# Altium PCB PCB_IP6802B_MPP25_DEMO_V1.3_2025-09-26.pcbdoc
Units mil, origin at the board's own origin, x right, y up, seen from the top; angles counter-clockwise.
Board outline 3349 x 3349 mil, 2 copper layers (Top Layer, Bottom Layer); 131 components, 91 nets, 373 pads, 326 vias.
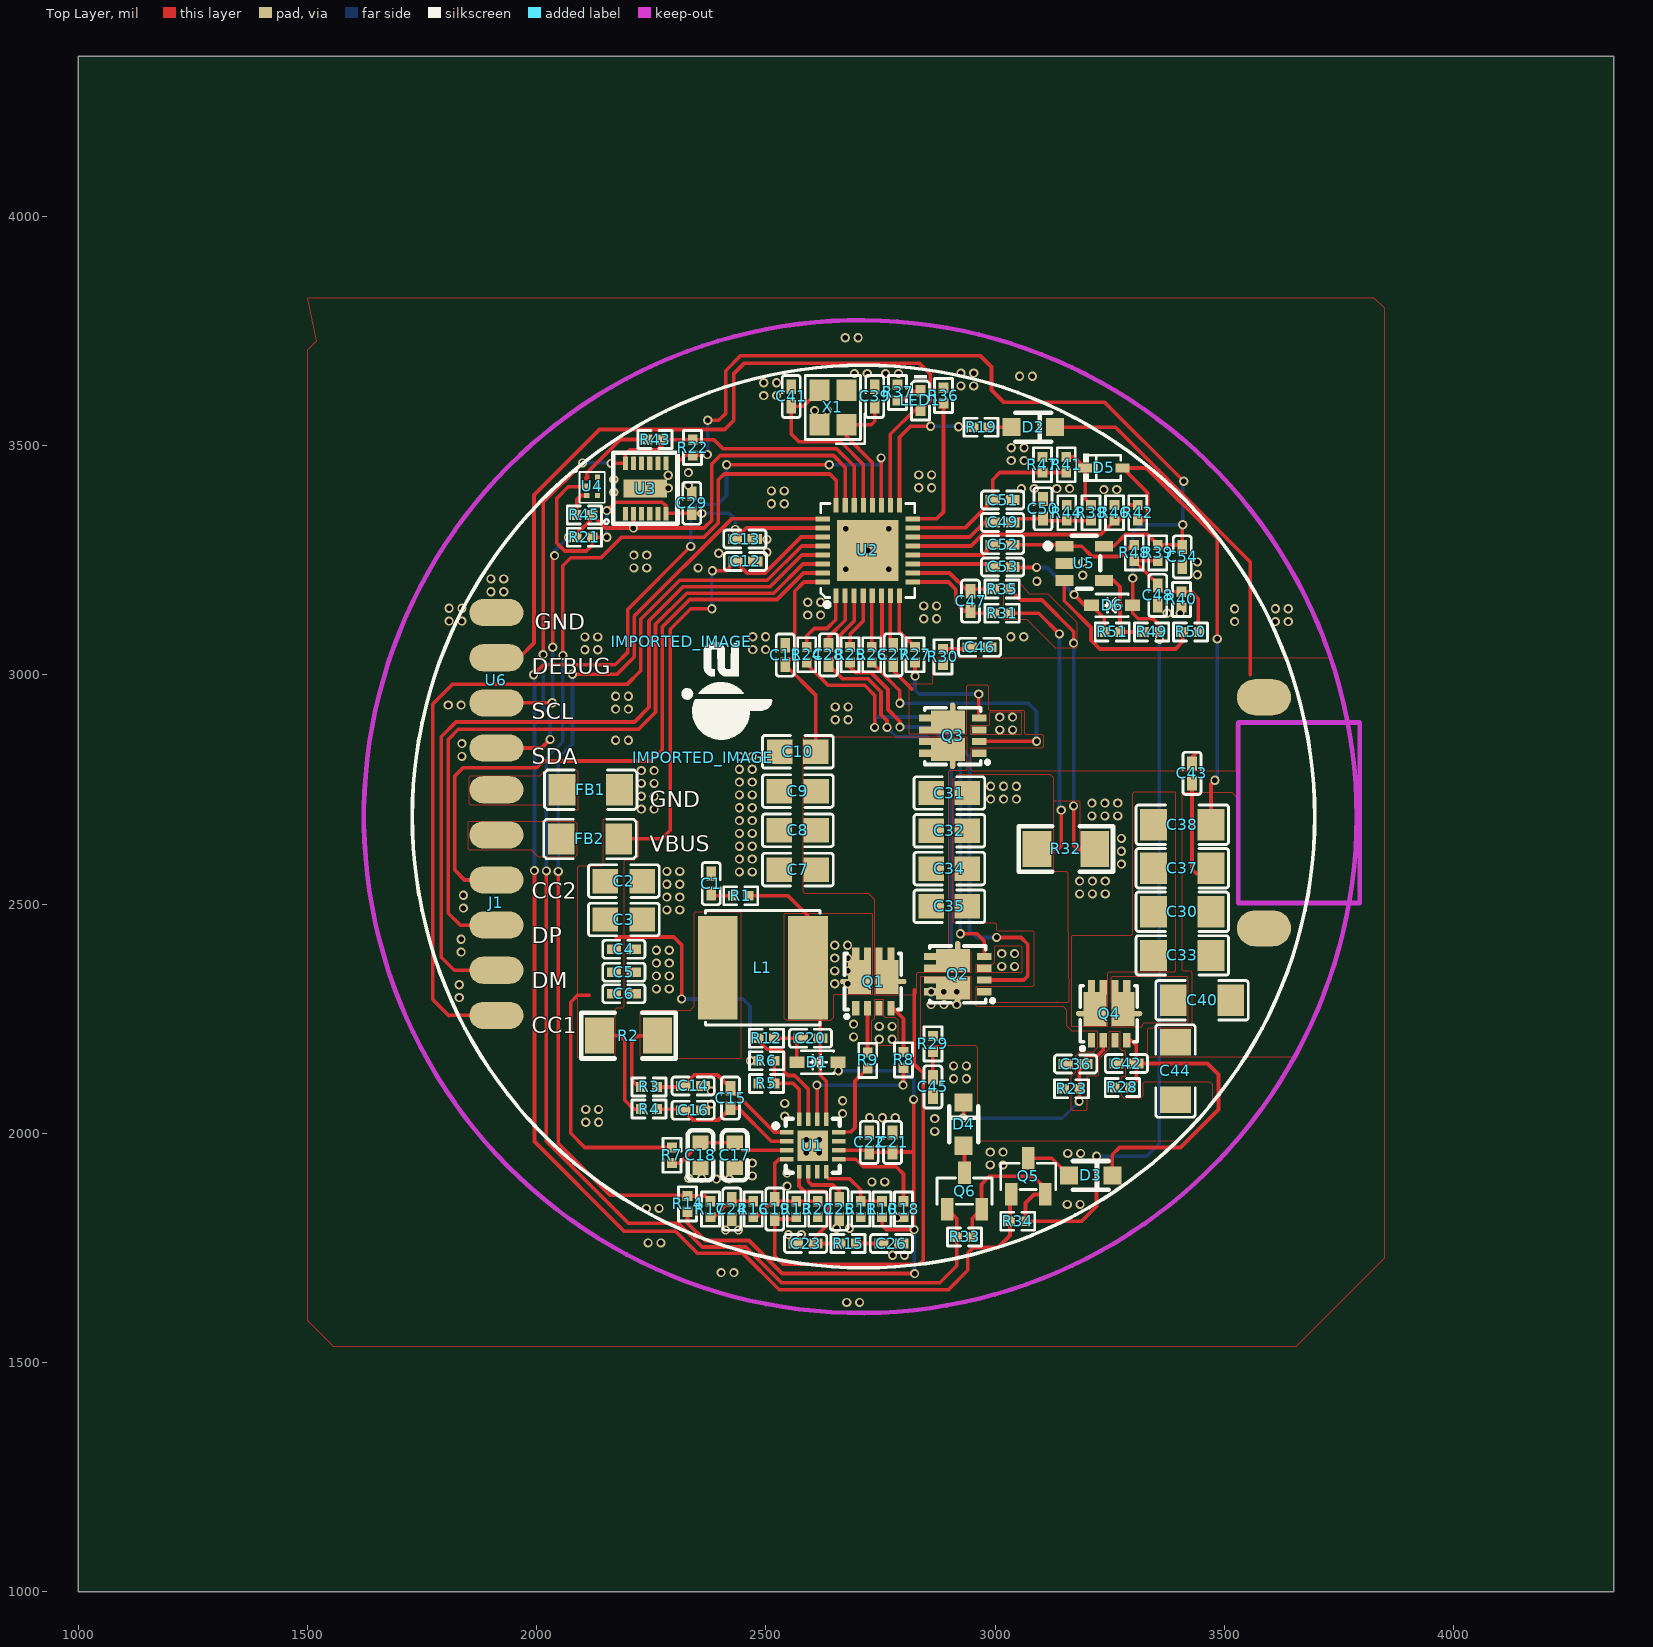
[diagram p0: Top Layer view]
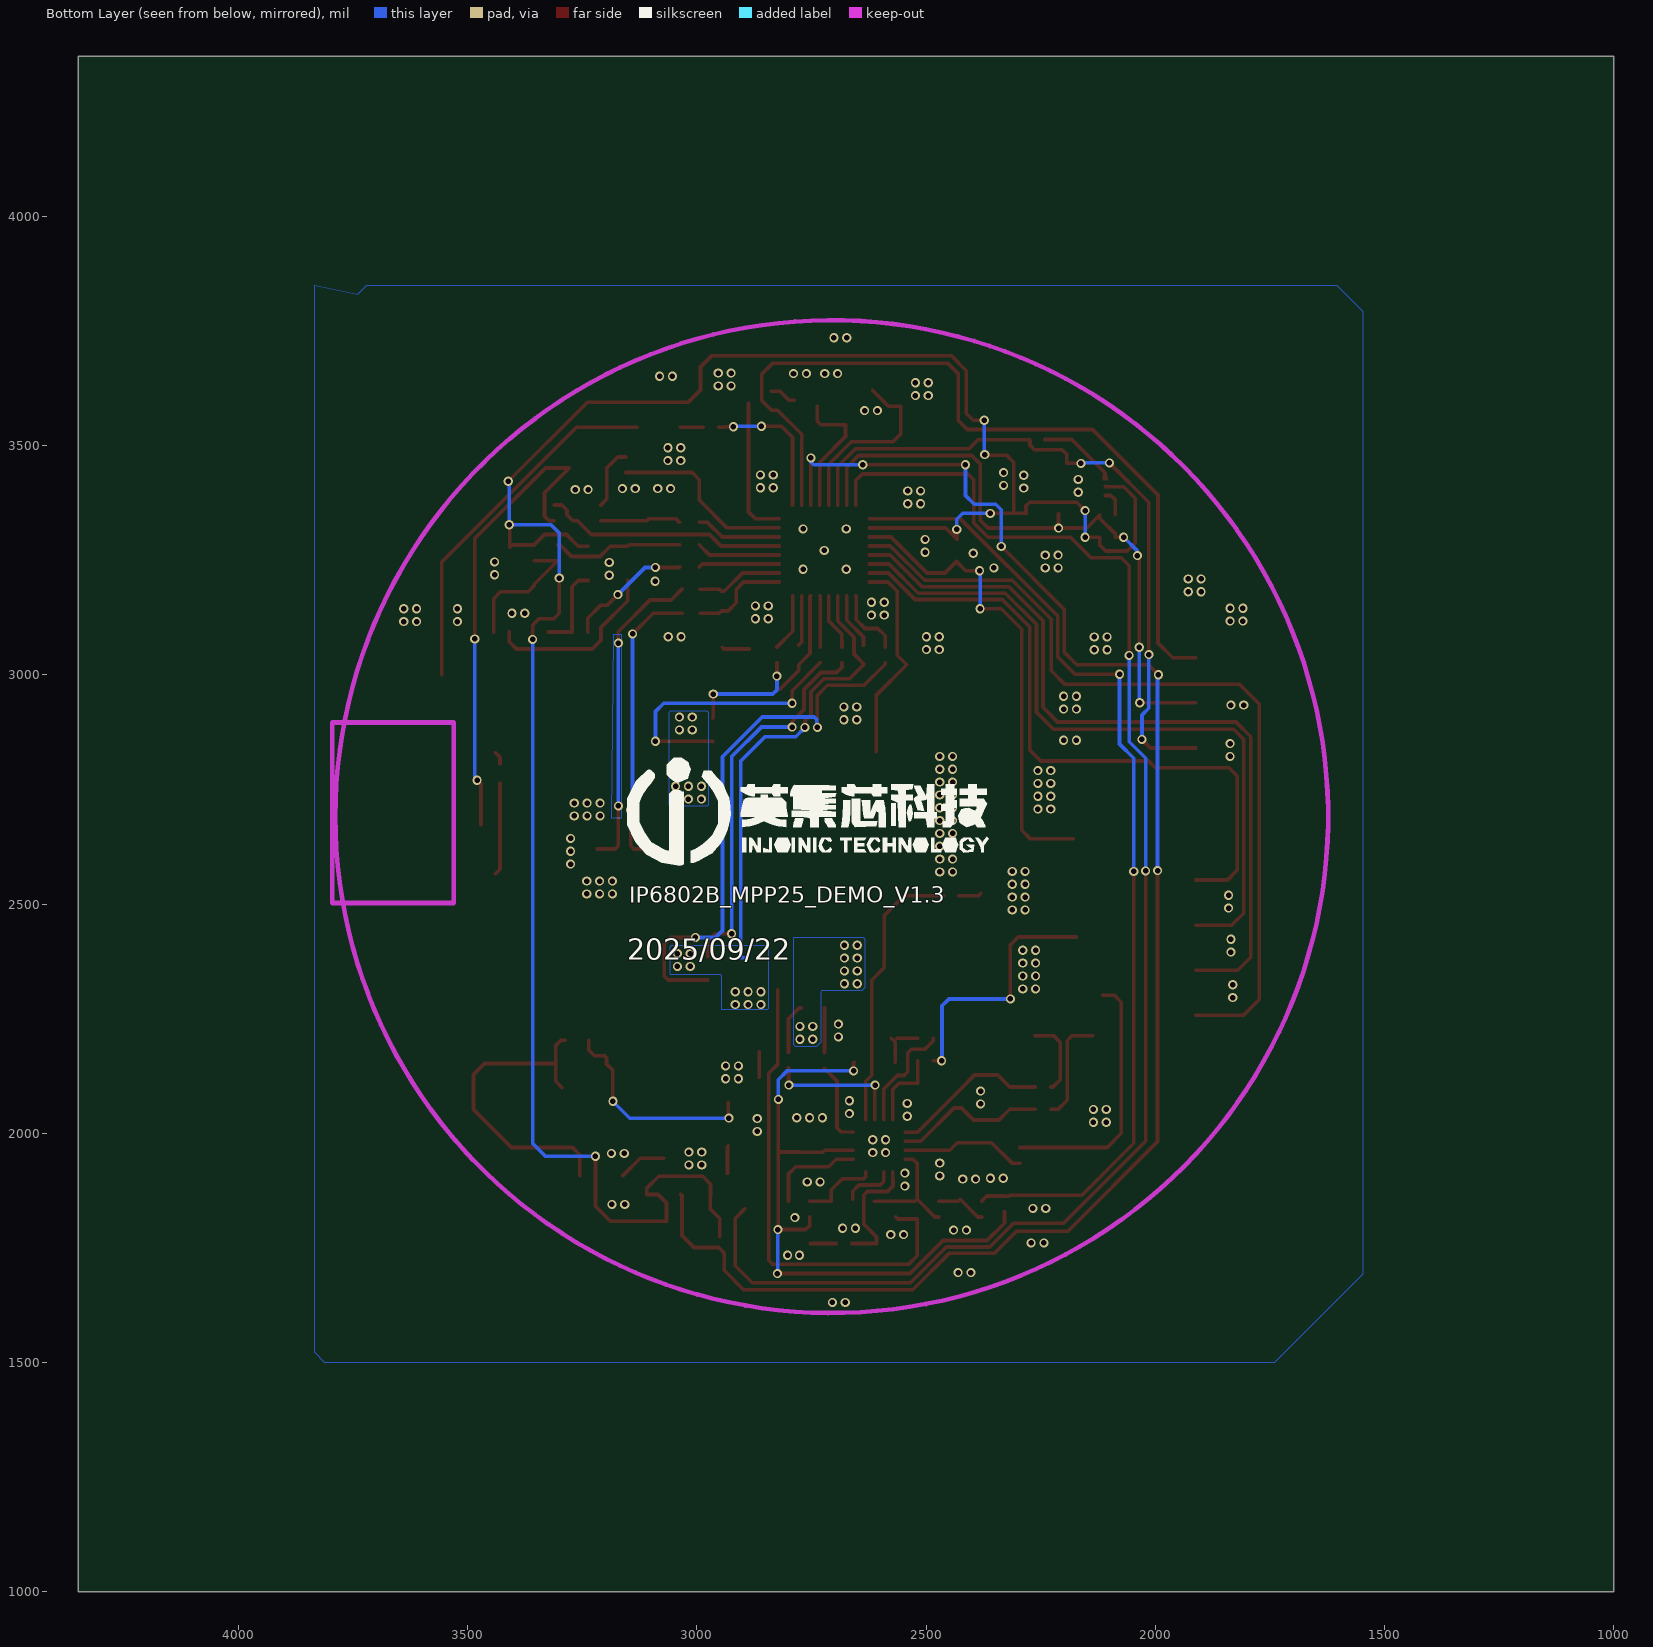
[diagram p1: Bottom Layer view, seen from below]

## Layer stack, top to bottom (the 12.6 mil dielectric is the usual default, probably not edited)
Top Layer: signal copper (thickness not stored)
Dielectric: dielectric 12.6, FR-4, Dk 4.8
Bottom Layer: signal copper (thickness not stored)

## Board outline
4349,1000 1000,1000 1000,4349 4349,4349

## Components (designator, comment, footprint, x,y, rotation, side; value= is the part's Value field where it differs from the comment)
C1 "NC" C0402 2380.5,2544.4 r270 top
C2 "22uF/16V" C0805#1 2190,2550 r0 top
C3 "22uF/16V" C0805#1 2190,2466.2 r0 top
C4 "4.7uF/16V" C0402 2190,2401.2 r0 top
C5 "4.7uF/16V" C0402 2190,2351.2 r0 top
C6 "100nF/16V" C0402 2190,2304.2 r0 top
C7 "22uF/25V" C0805#1 2569.5,2575 r180 top
C8 "22uF/25V" C0805#1 2569.5,2660.7 r180 top
C9 "22uF/25V" C0805#1 2569.5,2746.3 r180 top
C10 "22uF/25V" C0805#2 2569.5,2832 r180 top
C11 "4.7uF/25V" C0402 2542,3043 r270 top
C12 "4.7uF/16V" C0402 2455,3247 r180 top
C13 "4.7uF/6.3V" C0402 2454,3296 r180 top
C14 "15nF/16V" C0402 2341,2103.1 r0 top
C15 "4.7nF/16V" C0402 2422.7,2076.8 r90 top
C16 "15nF/16V" C0402 2341,2050.4 r0 top
C17 "10uF/16V" C0603 2431.7,1952 r270 top
C18 "10uF/16V" C0603 2357,1952 r270 top
C19 "NC" C0402 2519.2,1834.5 r90 top
C20 "100nF/16V" C0402 2597,2207.1 r0 top
C21 "2.2uF/6.3V" C0402 2776,1980 r270 top
C22 "100nF/16V" C0402 2725,1980 r270 top
C23 "10pF/50V" C0402 2586.4,1759.5 r180 top
C24 "100nF/16V" C0402 2425.6,1834.5 r270 top
C25 "100nF/16V" C0402 2659.6,1834.5 r270 top
C26 "3.3nF/50V" C0402 2773.6,1759.5 r0 top
C27 "100nF/16V" C0402 2777.8,3043.5 r90 top
C28 "100nF/16V" C0402 2636.2,3043.5 r90 top
C29 "100nF/16V" C0402 2338,3374 r270 top
C30 "100nF/NPO/100V" C1206 3408,2483 r0 top
C31 "22uF/25V" C0805#2 2900,2742 r0 top
C32 "22uF/25V" C0805#2 2900,2659.7 r0 top
C33 "100nF/NPO/100V" C1206 3408,2388 r0 top
C34 "22uF/25V" C0805#2 2900,2577.3 r0 top
C35 "22uF/25V" C0805#2 2900,2495 r0 top
C36 "100nF/16V" C0402 3175.2,2151 r0 top
C37 "100nF/NPO/100V" C1206 3408,2578 r0 top
C38 "100nF/NPO/100V" C1206 3408,2673 r0 top
C39 "22pF/50V" C0402 2737,3606.9 r90 top
C40 "33nF/NPO/100V" C1206 3450.92,2290 r0 top
C41 "22pF/50V" C0402 2555,3606.9 r270 top
C42 "100nF/16V" C0402 3286,2152 r0 top
C43 "NC" C0402 3429,2785 r90 top
C44 "68nF/NPO/100V" C1206 3393,2136 r90 top
C45 "NC" C0402 2864,2101 r90 top
C46 "NC" C0402 2966,3060 r180 top
C47 "4.7uF/6.3V" C0402 2946.2,3160.4 r270 top
C48 "1uF/6.3V" C0402 3354.5,3173 r270 top
C49 "10nF/50V" C0402 3016,3332.3 r180 top
C50 "10nF/50V" C0402 3104,3362 r270 top
C51 "2.2nF/50V" C0402 3016,3381 r180 top
C52 "10nF/50V" C0402 3016,3283.7 r0 top
C53 "10nF/50V" C0402 3016,3235 r180 top
C54 "1uF/6.3V" C0402 3408,3256.95 r90 top
D1 "1N4148W" SOD-323_L1.7-W1.3-LS2.6-FD-1 2612.18,2155.02 r180 top
D2 "IN5819" SOD-323FH_L2.0-W1.3-LS2.7-RD 3082.96,3540 r180 top
D3 "IN5819" SOD-323FH_L2.0-W1.3-LS2.7-RD 3208,1908 r180 top
D4 "1N4148W" SOD-323FH_L2.0-W1.3-LS2.7-RD 2931,2020 r270 top
D5 "1N4148/100V" SOD-323_L1.7-W1.3-LS2.5-FD 3237,3451 r180 top
D6 "1N4148W" SOD-323_L1.7-W1.3-LS2.6-FD-1 3254.98,3151.22 r180 top
FB1 "0Ω" L1206 2118,2749 r0 top
FB2 "0Ω" L1206 2116,2642 r0 top
IMPORTED_IMAGE "IMPORTED_IMAGE" IMPORTED_IMAGE 2315.84,3071.75 r0 top
IMPORTED_IMAGE "IMPORTED_IMAGE" IMPORTED_IMAGE 2363.7,2819.53 r0 top
J1 "6P焊盘" 6P焊盘 1912,2454 r0 top
L1 "2.2uH" IND-SMD_L6.0-W6.0 2493.01,2361 r0 top
LED1 "LED" LED0402-RD-1-2 2837,3598.16 r270 top
Q1 "AET3125BP" PDFN3333-8_L3.1-W3.1-P0.65-LS3.4-BL-EP 2733.96,2331 r0 top
Q2 "AET3125BP" PDFN3333-8_L3.1-W3.1-P0.65-LS3.4-BL-EP 2918,2347 r90 top
Q3 "AET3125BP" PDFN3333-8_L3.1-W3.1-P0.65-LS3.4-BL-EP 2907,2867 r90 top
Q4 "AER6125AP" PDFN3333-8_L3.1-W3.1-P0.65-LS3.4-BL-EP 3248.2,2261 r0 top
Q5 "BSS84 PD" SOT-23-3_L2.9-W1.3-P0.95-LS2.4-BR-1 3072,1906 r270 top
Q6 "BSS84 PD" SOT-23-3_L2.9-W1.3-P0.95-LS2.4-BR-1 2933,1874.07 r270 top
R1 "NC" R0402 2445,2518 r180 top
R2 "1.5mR/1%" R1206_1 2200,2213 r180 top
R3 "0R/1%" R0402 2245,2101 r0 top
R4 "0R/1%" R0402 2245,2052.7 r0 top
R5 "NC" R0402 2501,2108.8 r0 top
R6 "20K/1%" R0402 2501,2157.9 r0 top
R7 "0R/1%" R0402 2295,1952 r270 top
R8 "0R/1%" R0402 2800,2160 r270 top
R9 "0R/1%" R0402 2722,2159 r90 top
R10 "0R/1%" R0402 2753.2,1834.5 r90 top
R11 "NC" R0402 2706.4,1834.5 r270 top
R12 "0R/1%" R0402 2501,2207 r0 top
R13 "120K/1%" R0402 2566,1834.5 r270 top
R14 "10K/1%" R0402 2329,1846 r90 top
R15 "18K/1%" R0402 2679,1759.5 r0 top
R16 "10K/1%" R0402 2472.4,1834.5 r90 top
R17 "27K/1%" R0402 2378.8,1834.5 r90 top
R18 "200K/1%" R0402 2800,1834.5 r270 top
R19 "100R/5%" R0402 2969,3540 r180 top
R20 "7.5K/1%" R0402 2612.8,1834.5 r270 top
R21 "4.7K/5%" R0402 2104,3300 r180 top
R22 "4.7K/5%" R0402 2340,3495.5 r90 top
R23 "10K/5%" R0402 3166.4,2097 r0 top
R24 "0R/1%" R0402 2589,3043.5 r90 top
R25 "0R/1%" R0402 2683.4,3043.5 r90 top
R26 "0R/1%" R0402 2730.6,3043.5 r90 top
R27 "0R/1%" R0402 2825,3043.5 r90 top
R28 "10K/5%" R0402 3277.2,2100 r0 top
R29 "NC" R0402 2864,2195 r270 top
R30 "NC" R0402 2886,3039 r90 top
R31 "2R/1%" R0402 3015,3134 r0 top
R32 "20mR" R1206_1 3154,2620 r180 top
R33 "100K/5%" R0402 2933,1774 r180 top
R34 "100K/5%" R0402 3049.09,1808 r180 top
R35 "2R/1%" R0402 3015,3186.8 r0 top
R36 "100K" R0402 2887,3609 r270 top
R37 "1K/1%" R0402 2787,3615.7 r270 top
R38 "510R/1%" R0402 3209,3353.2 r270 top
R39 "100K/1%" R0402 3354.5,3265.79 r270 top
R40 "100K/1%" R0402 3406,3164.16 r270 top
R41 "100K/1%" R0402 3155,3458 r90 top
R42 "51K/1%" R0402 3311,3353.2 r270 top
R43 "240R/1%" R0402 2258,3513 r0 top
R44 "NC" R0402 3156,3353.2 r90 top
R45 "240R/1%" R0402 2104,3348.6 r0 top
R46 "51K/1%" R0402 3260,3353.2 r270 top
R47 "6.8K/1%" R0402 3103,3458 r270 top
R48 "200K/1%" R0402 3303,3265.79 r90 top
R49 "4.7K/1%" R0402 3341,3093.4 r0 top
R50 "10K/1%" R0402 3426,3093.4 r180 top
R51 "5.1K/1%" R0402 3255,3093.4 r180 top
U1 "IP6752" TQFN-16_L3.0-W3.0-P0.50-BL-EP1.7 2601.97,1973.03 r270 top
U2 "IP6802" QFN-32_L5.0-W5.0-P0.50-BL-EP3.4 2722,3271 r0 top
U3 "FM1210" FM1230 2312,3329 r90 top
U4 "T91-206" DFN6_I2C 2097.2,3379.2 r0 top
U5 "BL321" SOT-23-5_L2.9-W1.6-P0.95-LS2.8-BR 3194.02,3242.97 r180 top
U6 "4P端口" 4P焊盘 1912,3037 r180 top
X1 "24M" CRYSTAL-SMD_4P-L2.5-W2.0-BL 2646,3582.88 r90 top

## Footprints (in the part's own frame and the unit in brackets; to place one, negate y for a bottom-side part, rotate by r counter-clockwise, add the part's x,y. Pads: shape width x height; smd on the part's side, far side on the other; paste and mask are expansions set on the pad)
4P焊盘 [mm]
  oval 3x1.5 smd paste+0 mask+0.051: 1(0,5) 2(0,2.5) 3(0,0) 4(0,-2.5)
6P焊盘 [mm]
  oval 3x1.5 smd paste+0 mask+0.102: 1(0,-5) 2(0,-2.5) 3(0,0) 4(0,2.5) 5(0,5) 6(0,7.5)
C0402 [mm]
  rect 0.79x0.54 smd paste-100 mask+0.051: 1(-0.545,0) 2(0.545,0)
  silkscreen extent -1.17,-0.5 1.17,0.5
C0603 [mm]
  rect 0.8x0.9 smd paste+0 mask+0.051: 1(-0.7,0) 2(0.7,0)
  silkscreen extent -1.39,-0.71 1.39,0.71
C0805#1 [mm]
  rect 1.41x1.35 smd paste-100 mask+0.051: 1(-1.03,0) 2(1.03,0)
  silkscreen extent -1.96,-0.9 1.96,0.9
C0805#2 [mm]
  rect 1.41x1.35 smd paste-100 mask+0.051: 1(-1,0) 2(1,0)
  silkscreen extent -1.96,-0.9 1.96,0.9
C1206 [mm]
  rect 1.485x1.728 smd paste-100 mask+0.051: 1(-1.593,0) 2(1.593,0)
  silkscreen extent -2.56,-1.09 2.56,1.09
CRYSTAL-SMD_4P-L2.5-W2.0-BL [mm]
  rect 1.2x1.1 smd paste+0 mask+0.051: 1(-0.95,-0.75) 2(0.95,-0.75) 3(0.95,0.75) 4(-0.95,0.75)
  silkscreen extent -2.01,-1.76 1.78,1.53
DFN6_I2C [mm]
  rect 0.3x0.3 smd paste+0 mask+0.051: 2(0.3,0.8) 3(0.3,0.3) 4(0.9,0.3) 5(0.9,0.8) 6(0.9,1.3)
  Top Layer region: 0.3,1.45 0.45,1.45 0.45,1.15 0.15,1.15 0.15,1.3
  silkscreen extent -0.34,-0.1 1.3,1.69
FM1230 [mm]
  rect 0.75x0.29 smd paste+0: 1(0.559,3.014) 2(0.559,2.564) 3(0.559,2.114) 4(0.559,1.664) 5(0.559,1.214) 6(0.559,0.764) 7(3.353,0.764) 8(3.353,1.214) 9(3.353,1.664) 10(3.353,2.114) 11(3.353,2.564) 12(3.353,3.014)
  rect 1x2.4 smd paste+0: 13(1.968,1.905)
  silkscreen extent 0,0.13 3.94,4.19
IMPORTED_IMAGE [mil]
  silkscreen extent 0,-214 198,0
IND-SMD_L6.0-W6.0 [mm]
  rect 2.2x5.72 smd paste+0 mask+0.051: 1(-2.5,0) 2(2.5,0)
  silkscreen extent -3.18,-3.18 3.18,3.18
L1206 [mm]
  rect 1.485x1.728 smd paste-100 mask+0.051: 1(-1.593,0) 2(1.593,0)
  silkscreen extent -2.56,-1.09 2.56,1.09
LED0402-RD-1-2 [mm]
  rect 0.636x0.54 smd paste-100 mask+0.051: 1(0.538,0) 2(-0.538,0)
  silkscreen extent -1.39,-0.54 1.09,0.54
PDFN3333-8_L3.1-W3.1-P0.65-LS3.4-BL-EP [mm]
  rect 0.4x0.8 smd paste-100 mask+0.051: 1(-0.975,-1.47) 2(-0.325,-1.47) 3(0.325,-1.47) 4(0.975,-1.47) 5(0.975,1.47) 6(0.325,1.47) 7(-0.325,1.47) 8(-0.975,1.47)
  rect 1.275x1.88 smd paste-100 mask+0.05: 6(0.765,0.254)
  oval 0.635x0.3 smd paste-100 mask+0.05: 6(1.524,0) 8(-1.524,0)
  rect 1.275x1.88 smd paste-100 mask+0.051: 8(-0.772,0.254)
  silkscreen extent -1.59,-2.03 1.56,1.55
QFN-32_L5.0-W5.0-P0.50-BL-EP3.4 [mm]
  rect 0.28x0.8 smd paste-100 mask+0.05: 1(-1.75,-2.5) 2(-1.251,-2.5) 3(-0.751,-2.5) 4(-0.251,-2.5) 5(0.249,-2.5) 6(0.749,-2.5) 7(1.249,-2.5) 8(1.749,-2.5) 17(1.752,2.5) 18(1.251,2.5) 19(0.752,2.5) 20(0.251,2.5) 21(-0.248,2.5) 22(-0.749,2.5) 23(-1.248,2.5) 24(-1.749,2.5)
  rect 0.8x0.28 smd paste-100 mask+0.05: 9(2.5,-1.748) 10(2.5,-1.248) 11(2.5,-0.748) 12(2.5,-0.248) 13(2.5,0.252) 14(2.5,0.752) 15(2.5,1.252) 16(2.5,1.752) 25(-2.5,1.75) 26(-2.5,1.25) 27(-2.5,0.75) 28(-2.5,0.25) 29(-2.5,-0.25) 30(-2.5,-0.75) 31(-2.5,-1.25) 32(-2.5,-1.75)
  rect 3.4x3.4 smd paste-100 mask+0.05: 33(0,0)
  silkscreen extent -2.6,-3.12 2.6,2.6
R0402 [mm]
  rect 0.566x0.54 smd paste-100 mask+0.051: 1(-0.433,0) 2(0.433,0)
  silkscreen extent -0.94,-0.5 0.94,0.5
R1206_1 [mil]
  rect 63x78.74 smd paste+0 mask+1.97: 1(-62.99,0) 2(62.99,0)
  silkscreen extent -103,-50 103,50
SOD-323_L1.7-W1.3-LS2.5-FD [mm]
  rect 0.78x0.5 smd paste+0 mask+0.051: 1(-1.04,0) 2(1.04,0)
  silkscreen extent -0.93,-0.78 1.15,0.78
SOD-323_L1.7-W1.3-LS2.6-FD-1 [mm]
  rect 0.83x0.63 smd paste+0 mask+0.05: 1(-1.14,0) 2(1.14,0)
  silkscreen extent -0.89,-0.63 0.89,0.64
SOD-323FH_L2.0-W1.3-LS2.7-RD [mm]
  rect 1x1 smd paste+0 mask+0.051: 1(-1.2,0) 2(1.2,0)
  silkscreen extent -1,-0.8 1,0.8
SOT-23-3_L2.9-W1.3-P0.95-LS2.4-BR-1 [mm]
  rect 1.25x0.7 smd paste+0 mask+0.051: 1(1,-0.95) 2(1,0.95) 3(-1,0)
  silkscreen extent -0.73,-1.53 0.73,1.53
SOT-23-5_L2.9-W1.6-P0.95-LS2.8-BR [mm]
  rect 1x0.6 smd paste+0 mask+0.05: 1(1.1,-0.95) 2(1.1,0) 3(1.1,0.95) 4(-1.1,0.95) 5(-1.1,-0.95)
  silkscreen extent -0.89,-1.52 2.16,1.4
TQFN-16_L3.0-W3.0-P0.50-BL-EP1.7 [mm]
  rect 0.25x0.75 smd paste-100 mask+0.051: 1(-0.748,-1.45) 2(-0.249,-1.45) 3(0.252,-1.45) 4(0.751,-1.45) 9(0.75,1.45) 10(0.25,1.45) 11(-0.25,1.45) 12(-0.749,1.45)
  rect 0.75x0.25 smd paste-100 mask+0.051: 5(1.45,-0.75) 6(1.45,-0.25) 7(1.45,0.25) 8(1.45,0.75) 13(-1.45,0.75) 14(-1.45,0.25) 15(-1.45,-0.25) 16(-1.45,-0.75)
  rect 1.7x1.7 smd paste-100 mask+0.051: 17(0,0)
  silkscreen extent -1.5,-2.17 1.5,1.5

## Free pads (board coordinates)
  oval 118.11x78.74 smd paste+0 mask+2: 2(3586,2447) 2(3586,2951.01)

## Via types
v1: diameter 20, hole 12, Top Layer to Bottom Layer, tented both sides, 326 vias

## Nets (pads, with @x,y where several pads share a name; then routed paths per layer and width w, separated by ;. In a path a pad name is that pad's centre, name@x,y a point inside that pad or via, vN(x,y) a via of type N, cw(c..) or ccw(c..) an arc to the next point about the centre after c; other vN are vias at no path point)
BIAS: C21.2 C22.2 D1.1 R10.1 R14.1 U1.10 | length 1437.5
  Top Layer w8: R14.1 2329,1804 2367,1766 2463,1766 2534.99,1694 v1(2824,1694) ; D1.1 2658,2154.09 v1(2658,2136) ; U1.10 2720.39,1963.15 C22.2 ; C22.2 C21.2 ; R10.1 2753.2,1798.8 2762,1790 v1(2823,1790) 2822,1791 2822,1959 ; C21.2@2776,1959 2822,1959 ; v1(2822,2074) 2822,1959
  Bottom Layer w8: v1(2658,2136) 2803,2136 2822,2117 v1(2822,2074) ; v1(2823,1790) 2823,1695 v1(2824,1694)
BST: R12.1 U1.15 | length 248.1
  Top Layer w8: R12.1 2484,2201 2502,2183 2532,2183 2540,2175 2540,2134 2548,2126 2563,2126 2592.2,2096.8 U1.15@2592.2,2030.1
BST1: C28.2 U2.2 | length 122.7
  Top Layer w8: C28.2 2636.2,3082.2 2672.7,3118.7 U2.2
BST2: C27.2 U2.7 | length 110.4
  Top Layer w8: U2.7 2771.16,3071.6 C27.2
C1_2: C1.2 R1.2 | length 49.5
  Top Layer w8: C1.2 2385.43,2517.99 R1.2
C26_1: C26.1 R15.2 | length 56.1
  Top Layer w8: R15.2 C26.1@2752.16,1759.5
C45_2: C45.2 R29.2 | length 55.5
  Top Layer w8: C45.2 R29.2
C46_2: C46.2 R30.2 | length 60.2
  Top Layer w8: R30.2 2940.58,3056.04 C46.2
CC1: J1.1 U2.28 | length 1856.5
  Top Layer w8: J1.1 1808,2257 1773,2292 1773,2936 1816,2979 2197,2979 2227,3009 2227,3121 2312,3206 2503,3206 2577.8,3280.8 U2.28
CC2: J1.4 U2.31 | length 1448
  Top Layer w8: J1.4 1842.6,2552.4 1821,2574 1821,2779 1839,2797 2000,2797 2015,2812 2250,2812 2274,2836 2274,3104 2334,3164 2524,3164 2581.8,3221.8 U2.31
COMP: C23.1 R15.1 U1.5 | length 274.4
  Top Layer w8: U1.5@2572.5,1915.9 2572,1885 2584,1873 2628,1873 2636,1865 2636,1802 2607.9,1773.9 C23.1 ; C23.1 R15.1
D1_2: C20.1 D1.2 R12.2 | length 101
  Top Layer w8: R12.2 2563.3,2207 C20.1@2563.5,2207.2 ; D1.2 2567.33,2198.89 C20.1
D3_2: D3.2 Q5.3 | length 104.2
  Top Layer w8: Q5.3 3123.39,1945.37 D3.2
D4_2: D4.2 Q6.3 | length 60.2
  Top Layer w8: D4.2 2933,1970.76 Q6.3
D5_2: D5.2 R38.1 R41.2 | length 137.2
  Top Layer w8: R41.2 3172.02,3475.04 D5.2 3196.06,3383.14 R38.1
D6_2: C53.1 D6.2 R51.2 | length 276.7
  Top Layer w8: C53.1 3038.46,3234 v1(3090,3234) ; v1(3172,3175) 3195.78,3151.22 D6.2 3238,3123.3 R51.2
  Bottom Layer w8: v1(3090,3234) 3113,3234 v1(3172,3175)
DM: J1.2 U2.29 | length 1719.2
  Top Layer w8: J1.2 1820.4,2355.6 1792,2384 1792,2865 1824,2897 2213,2897 2245,2929 2245,3118 2319,3192 2509,3192 2578.2,3261.2 U2.29
DP: J1.3 U2.30 | length 1582.3
  Top Layer w8: J1.3 1833,2454 1807,2480 1807,2859 1829,2881 2222,2881 2259,2918 2259,3110 2327,3178 2517,3178 2580.5,3241.5 U2.30
DRV1H: R25.2 U2.4 | length 123.7
  Top Layer w8: R25.2 2684,3089.1 2712.1,3117.2 U2.4
DRV1L: R24.2 U2.1 | length 155
  Top Layer w8: R24.2 2589,3085 2605,3101 2633,3101 2652,3120 2652,3171.48 U2.1
DRV2H: R26.2 U2.5 | length 112.5
  Top Layer w8: R26.2 2730.6,3171.39 U2.5
DRV2L: R27.2 U2.8 | length 126.3
  Top Layer w8: U2.8 2790.8,3094.7 R27.2
FB: C19.2 R13.1 R16.1 R20.1 U1.4 | length 265.9
  Top Layer w8: R16.1 2480.7,1817.46 C19.2 2523.62,1851.54 R13.1 R20.1 ; C19.2 2519.2,1934.2 2528.4,1943.4 U1.4
FB1_1: FB1.1 J1.6
FB2_1: FB2.1 J1.5
FOSC: R18.1 U1.9 | length 213.9
  Top Layer w8: U1.9 2695.5,1943.5 2712,1927 2784,1927 2800,1911 R18.1
GND: C1.1 C2.2 C3.2 C4.2 C5.2 C6.2 C7.2 C8.2 C9.2 C10.2 C11.1 C12.1 C13.1 C14.2 C16.2 C17.2 C18.2 C21.1 C22.1 C23.2 C24.2 C25.2 C26.2 C29.1 C39.2 C41.1 C45.1 C46.1 C48.2 C50.1 C51.1 C54.1 FB1.2 Q1.1 R5.1 R11.2 R18.2 R20.2 R32.1 R35.2 R36.1 R37.1 R40.2 R44.2 R46.1 R47.1 U1.11 U1.17 U2.33 U3.7 U3.13 U4.4 U4.5 U4.6 U5.2 U6.4 X1.2 X1.4 | length 693.3
  Top Layer w8: R35.2 3055.84,3163 3102,3163 3171,3094 v1(3171,3069) ; v1(3171,2714) 3171,2627 3178,2620 R32.1
  Bottom Layer w8: v1(3171,2714) v1(3171,3069)
  other v1: 2676,1631 2704,1631 2402,1696 2430,1696 2776,1734 2802,1734 2243,1761 2271,1761 2549,1779 2577,1779 2412,1789 2440,1789 2654,1793 2682,1793 2786,1816 2239,1836 2267,1836 3157,1845 3185,1845 2546,1885 2731,1894 2759,1894 2391.95,1899.99 2419.95,1899.99 2331.61,1901.99 2359.61,1901.99 2470,1907 2546,1913 2989,1931 3017,1931 2470,1935 3158,1956 3186,1956 2588.04,1957.97 2616.04,1957.97 2989,1959 3017,1959 2588.04,1985.97 2616.04,1985.97 2868,2004 2107,2024 2135,2024 2868,2032 2726,2034 2754,2034 2782,2034 2541,2037 2667,2043 2107,2052 2135,2052 2381,2064 2541,2065 2667,2071 2381,2092 2909,2119 2937,2119 2909,2147 2937,2147 2691,2210 2691,2238 1831,2296 2261,2315 2289,2315 1831,2324 2261,2343 2289,2343 2261,2371 2289,2371 1835,2395 2261,2399 2289,2399 1835,2423 2284,2487 2312,2487 1840,2491 2284,2515 2312,2515 1840,2519 3184,2522 3212,2522 3240,2522 2284,2543 2312,2543 3184,2550 3212,2550 3240,2550 2442,2570 2470,2570 2284,2571 2312,2571 3275,2587 2442,2598 2470,2598 3275,2615 2442,2626 2470,2626 3275,2643 2442,2654 2470,2654 2442,2682 2470,2682 3211,2692 3239,2692 3267,2692 2228,2707 2256,2707 2442,2710 2470,2710 3211,2720 3239,2720 3267,2720 2228,2735 2256,2735 2442,2738 2470,2738 2228,2763 2256,2763 2442,2766 2470,2766 2228,2791 2256,2791 2442,2794 2470,2794 1837,2822 2442,2822 2470,2822 1837,2850 2172,2857 2200,2857 2651,2902 2679,2902 2172,2925 2200,2925 2651,2930 2679,2930 1807,2934 1835,2934 2172,2953 2200,2953 2105,3054.5 2133,3054.5 2471,3055 2499,3055 2105,3082.5 2133,3082.5 2471,3083 2499,3083 3034,3083 3062,3083 3522,3116 3611,3116 3639,3116 1809,3117 1837,3117 2844,3122 2872,3122 2591,3130 2619,3130 3375,3134 3403,3134 3522,3144 3611,3144 3639,3144 1809,3145 1837,3145 2844,3150 2872,3150 2591,3158 2619,3158 1900,3181 1928,3181 3091,3204 1900,3209 1928,3209 3191,3217 3441,3218 2674,3230.11 2768,3230.11 2212,3233 2240,3233 2352,3233 3191,3245 3441,3246 2212,3261 2240,3261 2397,3265 2502,3267 2722,3271 2502,3295 2674,3318.11 2768,3318.11 2512,3373 2540,3373 2168,3398 2512,3401 2540,3401 3237,3404 3265,3404 3057,3406 3085,3406 3134,3406 3162,3406 2287,3407 2833,3408 2861,3408 2331,3413 2168,3426 2287,3435 2833,3436 2861,3436 2331,3441 3035,3467 3063,3467 3035,3495 3063,3495 2606,3576 2634,3576 2495,3609 2523,3609 2925,3630 2953,3630 2495,3637 2523,3637 3053,3651 3081,3651 2693,3657 2721,3657 2761,3657 2789,3657 2925,3658 2953,3658 2673,3735 2701,3735
GPIO1: R19.2 U2.17 | length 320.4
  Top Layer w8: U2.17 2791,3518 2815,3542 v1(2859,3542) ; v1(2920,3541) 2937,3541 2938,3540 R19.2
  Bottom Layer w8: v1(2859,3542) 2919,3542 v1(2920,3541)
IDEM1: C53.2 U2.11 | length 176.8
  Top Layer w8: U2.11 2987.99,3241.55 C53.2
ISNS1N: C47.1 R35.1 U2.10 | length 191.4
  Top Layer w8: U2.10 2900.13,3221.87 2940.14,3181.86 C47.1 2951.13,3186.78 R35.1@2993.16,3186.78
ISNS1O: C52.1 U2.12 | length 183.4
  Top Layer w8: U2.12 2972.1,3261.2 C52.1
ISNS1P: C47.2 R31.1 U2.9 | length 217
  Top Layer w8: U2.9 2897.8,3202.2 2914,3186 2914,3157 2932.1,3138.9 C47.2 ; C47.2 2951.13,3134.01 R31.1@2992.16,3134.01
LED1/DEBUG: LED1.1 U2.18 U6.3 | length 1800.5
  Top Layer w8: U6.3 1962,3037 1994,3069 1994,3392 2137,3535 2410,3535 2430,3555 2430,3657 2452,3679 2835,3679 2858,3656 2858,3598 LED1.1 ; U2.18 2771.27,3524.27 2823.97,3576.97 LED1.1
LX: C20.2 L1.2 Q1.3 Q1.7 Q1.8 R1.1 U1.13 | length 608.4
  Top Layer w8: R1.1 2548.01,2517.99 2591.42,2474.58 L1.2 2618.46,2333.96 C20.2 2618.46,2126.54 2631.5,2113.5 U1.13
  other v1: 2747,2205 2775,2205 2747,2233 2775,2233 2650,2326 2678,2326 2650,2354 2678,2354 2650,2382 2678,2382 2650,2410 2678,2410
NONET: 
NTC: R36.2 U2.16 | length 309.8
  Top Layer w8: U2.16 2872,3340 2887,3355 R36.2
OSC_IN: C39.1 U2.20 X1.1 | length 296.5
  Top Layer w8: U2.20 2731.9,3463.1 2675.5,3519.5 X1.1 2729.5,3545.5 2737,3553 C39.1
OSC_OUT: C41.2 U2.21 X1.3 | length 410.3
  Top Layer w8: C41.2 2555,3525 2572,3508 2663,3508 2712.2,3458.8 U2.21 ; C41.2 2581.62,3585.43 X1.3
PWM: R14.2 R17.2 U2.25 | length 2158.1
  Top Layer w8: v1(2047,2571) 2047,1978 2160,1865 2317,1865 2319,1863 R14.2 ; v1(2078,3001) 2175,3001 2212.9,3038.9 2212.9,3127.9 2424.9,3339.9 U2.25 ; R14.2 2367.3,1863.04 R17.2
  Bottom Layer w8: v1(2047,2571) 2047,2818 2078,2849 v1(2078,3001)
Q1_2: Q1.2 R9.2 | length 97.4
  Top Layer w8: Q1.2 2721.21,2176.83 R9.2
Q1_4: Q1.4 R8.1 | length 110.2
  Top Layer w8: Q1.4@2772.39,2273.13 2776.87,2273.13 2800,2250 R8.1
Q4_6: C40.1 Q4.5 Q4.6
Q4_8: C30.1 C33.1 C37.1 C38.1 Q4.7 Q4.8
QDET1: R42.1 R46.2 U2.13 | length 533.4
  Top Layer w8: U2.13 2946.92,3280.92 2972,3306 3229.88,3306 3260,3336.12 3270.1,3336.1 3283,3349 3283,3359 3294.2,3370.2 R42.1
R2_1: L1.1 R2.1 R3.1 | length 170.8
  Top Layer w8: R3.1 2223,2101 2207,2117 2207,2198 2222,2213 R2.1
R5_2: R5.2 R6.2 U1.16 | length 174.5
  Top Layer w8: R5.2 2559.2,2108.8 2572.5,2095.5 U1.16@2572.5,2030.1 ; R5.2 R6.2
R7_2: C17.1 C18.1 R7.2 U1.3 | length 275.2
  Top Layer w8: R7.2 2312.4,1934.96 C18.1 C17.1 2448.14,1963.09 U1.3
R10_2: R10.2 R11.1 U1.8 | length 169.1
  Top Layer w8: U1.8 2631.53,1905.47 2635.83,1901.17 2681.83,1901.17 2706.4,1876.6 R11.1 R10.2
R17_1: C24.1 R16.2 R17.1 | length 111.4
  Top Layer w8: R17.1 2387.1,1817.46 C24.1 2430.02,1851.54 R16.2
R19_1: D2.2 R19.1 | length 49.7
  Top Layer w8: R19.1 D2.2@3035.76,3540
R24_1: Q2.2 R24.1 | length 1197.4
  Top Layer w8: R24.1 2589,3022.9 2635.07,2976.83 2715.17,2976.83 2737,2955 v1(2737,2885) ; Q2.2 3062.2,2334.2 3071,2343 3071,2412 3056,2427 v1(3003,2427)
  Bottom Layer w8: v1@2738,2885 2738,2902 2744,2908 2857,2908 2944,2821 2944,2442 2959,2427 v1(3003,2427)
R25_1: Q2.4 R25.1 | length 842.5
  Top Layer w8: R25.1 2683.4,3016.6 2695,3005 2729,3005 2766,2968 2766,2924 2792,2898 v1(2792,2886) ; v1(2924,2435) 2960,2435 2975.87,2419.13 Q2.4
  Bottom Layer w8: v1(2792,2886) 2859,2886 2924,2821 v1(2924,2435)
R26_1: Q3.2 R26.1 | length 609.9
  Top Layer w8: R26.1 2792,2965.1 v1(2792,2938) ; Q3.2 2965.67,2855 v1(3090,2855)
  Bottom Layer w8: v1(2792,2938) 3072,2938 3090,2920 v1(3090,2855)
R27_1: Q3.4 R27.1 | length 255.2
  Top Layer w8: v1(2825,2997) R27.1 ; v1(2964,2958) 2964,2906.26 Q3.4
  Bottom Layer w8: v1(2825,2997) 2825,2967 2834,2958 v1(2964,2958)
R32_2: C31.2 C32.2 C34.2 C35.2 Q2.1 Q3.3 R31.2 R32.2 | length 646.2
  Top Layer w8: R31.2 3095,3134 v1(3140,3089) ; R32.2 3137,2620 3144,2627 v1(3144,2705)
  Bottom Layer w8: v1(3140,3089) 3140,2709 v1(3144,2705)
  other v1: 2990,2729 3018,2729 3046,2729 2990,2757 3018,2757 3046,2757 3009.74,2879.8 3037.74,2879.8 3009.74,2907.8 3037.74,2907.8
R37_2: LED1.2 R37.2 | length 58.1
  Top Layer w8: R37.2 2798.66,3598.66 2818.19,3618.19 LED1.2@2837,3618.19
R44_1: C49.1 C50.2 R38.2 R44.1 | length 176.8
  Top Layer w8: C49.1@3037.42,3332.3 3045.66,3340.54 C50.2 3108.42,3336.12 3156,3336.12 R38.2@3209,3336.12
R50_2: R50.2 U5.3 | length 390.6
  Top Layer w8: U5.3 3150.7,3161.3 3209,3103 3209,3075 3228,3056 3393,3056 3409,3072 R50.2
R51_1: R49.1 R51.1 U5.4 | length 190.9
  Top Layer w8: U5.4 3258.4,3205.6 3272,3192 R51.1 ; R51.1 R49.1
S1: Q6.1 R33.2 U2.24 | length 3234.8
  Top Layer w8: v1(2021,2572) 2021,1983 2200,1804 2309,1804 2361,1752 2456,1752 2534,1674 2879,1674 2916,1711 R33.2 ; v1(2057,3042) 2057,3238 2074,3255 2140,3255 2185,3300 2365,3300 2396,3331 2396,3425 2409,3438 2639,3438 2653.2,3423.8 U2.24 ; Q6.1 2915.96,1814.34 R33.2
  Bottom Layer w8: v1(2021,2572) 2020.99,2817.99 2057,2854 v1(2057,3042)
S1_CTL: C36.2 D4.1 Q4.2 R23.2 | length 470.7
  Top Layer w8: v1(2930,2033) 2931,2034 D4.1 ; v1(3183,2070) 3183,2096.56 R23.2 3183.44,2137.78 C36.2 3196.66,2164.66 3201,2169 3223,2169 3235.41,2181.41 Q4.2
  Bottom Layer w8: v1(2930,2033) 3146,2033 v1(3183,2070)
S2: Q5.1 R34.2 U2.19 | length 3556.2
  Top Layer w8: v1(1993,3000) 2015,3022 2171,3022 2198.8,3049.8 2198.8,3142.8 v1(2336,3280) ; v1(1995,2573) 1995,1982 2191,1786 2303,1786 2351,1738 2450.1,1738 2529.1,1659 2898,1659 2940,1701 2940,1739 2952,1751 3006,1751 3032,1777 R34.2 ; v1(2414,3458) v1(2638,3458) ; v1(2751,3473) 2751.59,3472.41 U2.19 ; R34.2 3032.05,1864.08 Q5.1
  Bottom Layer w8: v1(1993,3000) 1995,3000 v1(1995,2573) ; v1(2336,3280) 2336,3360 2348,3372 2395,3372 2414,3391 v1(2414,3458) ; v1(2638,3458) 2745,3458 2751,3464 v1(2751,3473)
S2_CTL: C42.2 D3.1 Q4.4 R28.2 | length 706.1
  Top Layer w8: D3.1 3255.2,1953.2 3271,1969 3404,1969 3487,2052 3487,2128 3463,2152 C42.2 ; Q4.4 3295.9,2203.1 3307.5,2191.5 C42.2 ; R28.2 3307.5,2113.2 C42.2
SCL: R21.2 R45.2 U2.23 U3.2 U6.2 | length 1404
  Top Layer w8: U6.2 2033.58,2938.58 v1(2034,2939) ; v1(2035,3060) 2035,3256 v1(2039,3260) ; v1(2069,3300) R21.2 ; R21.2 2087,3307 2121,3341 R45.2 2149.7,3320 v1(2211,3320) ; U3.2@2211,3351 v1(2211,3320) ; U2.23@2672.9,3369.4 2672.9,3452.2 2647,3478 2400,3478 2382,3460 2382,3337 2365,3320 v1(2211,3320)
  Bottom Layer w8: v1(2034,2939) 2035,2940 v1(2035,3060) ; v1(2039,3260) 2039,3270 v1(2069,3300)
SDA: R22.2 R43.2 U2.22 U3.12 U6.1 | length 1511
  Top Layer w8: U6.1 2010.15,2840.15 v1(2029,2859) ; v1(2014,3044) 2014,3376 v1(2100,3462) ; v1(2162,3461) U3.12 2193.34,3480.99 2203.34,3490.99 2263.34,3490.99 2273.34,3500.99 2273.34,3511.3 R43.2 ; R43.2 R22.2 2386.5,3512.5 2406,3493 2654,3493 2692.5,3454.5 U2.22
  Bottom Layer w8: v1(2014,3044) 2014,2927 2029,2912 v1(2029,2859) ; v1(2100,3462) 2161,3462 v1(2162,3461)
SS: C25.1 U1.6 | length 114.8
  Top Layer w8: U1.6@2592.2,1915.9 2592,1895 2599.9,1887.1 2645.9,1887.1 2659.6,1873.4 C25.1
SW1: C28.1 C36.1 C42.1 C44.1 Q2.3 Q2.7 Q2.8 Q4.1 Q4.3 R23.1 R28.1 R29.1 U2.3 | length 1006.8
  Top Layer w8: U2.3 2692.42,3117.42 2657,3082 2657,3045 2636.2,3024.2 C28.1 2667.31,2990.93 2723.17,2990.93 2751,2963.1 2751,2913 2764,2900 v1(2764,2885)
  Bottom Layer w8: v1(2764,2885) 2784,2865 2851,2865 2904,2812 2904,2383 2893,2383
  other v1: 2860.13,2280.61 2888.13,2280.61 2916.13,2280.61 2860.13,2308.61 2888.13,2308.61 2916.13,2308.61 3014.04,2364 3042.04,2364 3014.04,2392 3042.04,2392
SW2: C27.1 C43.2 D2.1 pad.2@3586,2951.01 Q3.1 Q3.5 Q3.6 R30.1 U2.6 | length 1052.4
  Top Layer w8: U2.6 2753,3171.1 2753,3046.8 C27.1 ; C27.1 2777.8,3009.2 2818,2969 ; D2.1 3262,3540 3556,3246 3556,3000 ; C43.2 3429,2820 3439,2830
U1_1: C14.1 C15.2 R3.2 U1.1 | length 345.3
  Top Layer w8: R3.2 2317.39,2101 C14.1@2319.54,2103.15 ; C14.1 2343.4,2127 2394,2127 C15.2@2422.7,2098.2 ; C15.2 2518.5,2002.5 U1.1
U1_2: C15.1 C16.1 R4.2 U1.2 | length 333.6
  Top Layer w8: R4.2 2317.26,2052.67 C16.1 ; C16.1 2340.9,2029 2396.4,2029 C15.1 2438.7,2055.3 2511.2,1982.8 U1.2
U1_7: U1.7
U1_12: R9.1 U1.12 | length 180.2
  Top Layer w8: U1.12 2685,2003 2694,2012 2694,2114 R9.1
U1_14: R8.2 U1.14 | length 301.7
  Top Layer w8: v1(2611,2105) 2611.85,2104.15 U1.14@2611.85,2030.09 ; v1(2799,2105) 2799,2113 2800,2114 R8.2
  Bottom Layer w8: v1(2611,2105) v1(2799,2105)
U3_1: U3.1
U3_3: U3.3
U3_4: U3.4
U3_5: U3.5
U3_8: U3.8
U3_9: U3.9
U3_10: U3.10
U3_11: U3.11
U4_1: R43.1 | length 171.8
  Top Layer w8: 2109,3430.4 2109,3440 2182,3513 R43.1
U4_3: R45.1 U4.3 | length 58.5
  Top Layer w8: R45.1 2087,3381 2097,3391 U4.3
U5_1: C52.2 R48.2 U5.1 | length 286.4
  Top Layer w8: C52.2 3147.42,3283.67 U5.1 ; U5.1 3188.64,3280.36 3211,3258 3273,3258 3297.83,3282.83 R48.2
VBUS: C2.1 C3.1 C4.1 C5.1 C6.1 C12.2 FB2.2 R2.2 R4.1 R6.1 R7.1 U2.27 | length 2405.2
  Top Layer w8: 2114,2301 2089,2301 2074,2286 2074,2000 2105,1969 R7.1 ; R2.2 2181,2213 2192,2202 2192,2072 2211.3,2052.7 R4.1 ; 2172,2428 2299,2428 2316,2411 v1(2316,2293) ; FB2.2 2272,2642 2291,2661 2291,3099 2336,3144 v1(2382,3144) ; v1(2383,3227) 2413.54,3227 C12.2 2458.54,3222 2498,3222 2576.53,3300.53 U2.27 ; v1(2466,2158) 2483.86,2158 R6.1
  Bottom Layer w8: v1(2316,2293) 2450,2293 2465,2278 2465,2159 v1(2466,2158) ; v1(2382,3144) 2382,3226 v1(2383,3227)
VC1: C30.2 C33.2 C37.2 C38.2 C40.2 C43.1 C44.2 D5.1 pad.2@3586,2447 R42.2 | length 1253.6
  Top Layer w8: R42.2@3311,3336.1 3322.1,3336.1 3332,3346 3332,3396.9 D5.1 3330,3451 3484,3297 v1(3484,3078) ; C43.1 3429,2576 3439,2566 ; C38.2 3470.7,2761.7 v1(3479,2770)
  Bottom Layer w8: v1(3479,2770) 3484,2775 v1(3484,3078)
VCC: C13.2 C29.2 C54.2 D6.1 Q5.2 Q6.2 R21.1 R22.1 R33.1 R34.1 R39.1 R49.2 U2.26 U3.6 U4.2 U5.5 | length 5134.3
  Top Layer w8: U4.2@2109,3411 2108,3410 2069,3410 2044,3385 2044,3287 2061,3270 2108,3270 2121,3283 R21.1 ; R21.1 v1(2153,3300) ; v1(2153,3358) 2171,3376 2274,3376 2281.92,3368.08 U3.6 2283.47,3352.54 C29.2 2338.54,3352 v1(2360,3352) ; 2308.7,3352.5 2308.7,3463.7 2323.4,3478.4 2340,3478.4 2370.41,3478.41 v1(2372,3480) ; v1(2373,3555) 2397,3555 2412,3570 2412,3663 2445,3696 2967,3696 2992,3671 2992,3621 3019,3594 3239,3594 v1(3411,3422) ; v1(2433,3317) 2432.54,3316.54 C13.2 2456.75,3320.21 U2.26 ; R33.1 2950.04,1814.34 Q6.2 2970,1889 2987,1906 3072,1906 3083,1906 3109.4,1879.6 Q5.2 3084.6,1866.6 3066.1,1848.1 R34.1 3188,1808 3221,1841 v1(3221,1950) ; U5.5 3258.4,3280.4 3284,3306 3332,3306 R39.1@3355,3282.8 ; v1(3300,3211) 3300,3151.37 3299.85,3151.22 3299.85,3134.15 3312,3122 3343.99,3122 3358,3107.99 v1(3358,3077) R49.2 R49.2 ; R39.1@3355,3282.83 3403.58,3282.83 C54.2 3408,3326 v1(3409,3327)
  Bottom Layer w8: v1(2153,3300) v1(2153,3358) ; v1(2360,3352) 2420,3352 2433,3339 v1(2433,3317) ; v1(2372,3480) 2373,3481 v1(2373,3555) ; v1(3221,1950) 3330,1950 3358,1978 v1(3358,3077) ; v1(3300,3211) 3300,3309 3318,3327 v1(3409,3327) 3409,3420 v1(3411,3422)
VCOIL1: C51.2 R41.1 R47.2 U2.15 | length 410.6
  Top Layer w8: U2.15 2933.8,3320.3 C51.2 2994.5,3425.5 3009.96,3440.96 R47.2 R41.1
VDEM1: C49.2 U2.14 | length 187.2
  Top Layer w8: U2.14 2944.6,3300.6 2976.3,3332.3 C49.2
VOUT: C7.1 C8.1 C9.1 C10.1 C11.2 C19.1 C31.1 C32.1 C34.1 C35.1 Q1.5 Q1.6 Q2.5 Q2.6 Q3.7 Q3.8 R13.2 U2.32 | length 1517.7
  Top Layer w8: C19.1 2519.2,1732.8 2538,1714 2834,1714 2843,1723 2843,2131 2823,2151 2823,2313 ; C19.1 2561.58,1813.04 R13.2 ; C10.1 2608.87,2954.67 C11.2 2563,3042.54 2563,3182 2583.1,3202.1 U2.32
VREF: C48.1 R39.2 R40.1 R48.1 R50.1 | length 300
  Top Layer w8: R39.2 R48.1 3354.5,3197.25 C48.1 3367.76,3181.2 R40.1 3427.9,3181.2 3443,3166 R50.1

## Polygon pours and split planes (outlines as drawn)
FB1_1 on Top Layer (solid): 1857,2780 2007,2780 2021,2794 2084,2794 2090,2788 2090,2706 2089,2705 2027,2705 2017,2715 1858,2715 1857,2715 1853,2719 1853,2777 1856,2780
FB2_1 on Top Layer (solid): 1855,2681 2082,2681 2087,2676 2087,2607 2087,2606 2083,2602 2004,2602 1989,2617 1862,2617 1854,2617 1851,2620 1851,2679 1853,2681
VBUS on Top Layer (solid): 2150,2686 2214,2686 2221,2679 2221,2603 2213,2595 2193,2595 2190,2592 2190,2276 2187,2273 2174,2273 2170,2269 2170,2170 2166,2166 2090,2166 2089,2165 2089,2580 2092,2583 2117,2583 2142,2583 2145,2586 2145,2684 2147,2686
R2_1 on Top Layer (solid): 2445,2164 2443,2162 2233,2162 2226,2169 2226,2265 2229,2268 2335,2268 2344,2277 2344,2480 2347,2483 2443,2483 2445,2481 2445,2164
LX on Top Layer (solid): 2541,2479 2542,2480 2730,2480 2732,2478 2732,2302 2673,2302 2649,2302 2647,2300 2647,2252 2640,2245 2546,2245 2540,2251 2540,2478
VOUT on Top Layer (solid): 2828,2304 2825,2301 2737,2301 2737,2509 2724,2522 2586,2522 2581,2527 2581,2860 2586,2865 2938,2865 2938,2794 2935,2791 2900,2791 2897,2788 2897,2401 2899,2399 2943,2399 2947,2395 2947,2350 2831,2350 2828,2347
LX on Top Layer (solid): 2736,2291 2736,2250 2730,2244 2730,2197 2735,2192 2780,2192 2788,2200 2788,2246 2782,2252 2760,2252 2757,2255 2757,2291
R32_2 on Top Layer (solid): 2912,2458 2908,2462 2908,2771 2920,2783 3119,2783 3126,2776 3126,2574 3129,2571 3155,2571 3158,2568 3158,2487 3160,2288 3157,2285 2959,2285 2959,2321 3082,2321 3085,2324 3085,2438 3082,2441 3006,2441 3003,2443 3003,2455 3000,2458 2912,2458
R32_2 on Top Layer (solid): 2947.74,2889.8 2985.74,2889.8 2987.74,2891.8 2987.74,2916.8 2989.74,2918.8 3054.74,2918.8 3056.74,2916.8 3056.74,2870.8 3054.74,2868.8 2993.74,2868.8 2946.74,2868.8
SW2 on Top Layer (solid): 2951,2790 2948,2793 2948,2841 3103,2841 3106,2844 3106,2866 3103,2869 3067,2869 3064,2872 3064,2919 3061,2922 2989,2922 2986,2925 2986,2974 2983,2977 2940,2977 2937,2974 2937,2870 2815,2870 2812,2870 2812,2977 2815,2980 2862,2980 2864,2982 2864,3034 2867,3037 3730,3037 3770,2894 3527,2895 3525,2893 3525,2819 3525,2816 3525,2790
NONET on Top Layer (solid): 3127,2612 3184,2612 3185,2613 3185,2722 3183,2724 3129,2724 3126,2721 3126,2624
SW1 on Top Layer (solid): 2960.04,2369 2995.04,2369 2999.04,2373 2999.04,2407 3001.04,2409 3056.04,2409 3058.04,2407 3058.04,2352 3056.04,2350 2960.04,2350 2959.04,2351 2959.04,2369
Q4_8 on Top Layer (solid): 3167,2232 3167,2430 3169,2432 3297,2432 3300,2435 3300,2436 3300,2742 3303,2745 3391,2745 3394,2742 3393,2741 3393,2354 3390,2351 3247,2351 3244,2348 3244,2232 3167,2232
Q4_6 on Top Layer (solid): 3321,2234 3318,2231 3254,2231 3253,2339 3256,2342 3417,2342 3420,2339 3420,2243 3417,2240 3324,2240 3321,2237
VC1 on Top Layer (solid): 3661,2178 3655,2166 3336,2166 3333,2169 3333,2227 3336,2230 3427,2230 3430,2233 3430,2350 3427,2353 3411,2353 3408,2356 3408,2743 3409,2744 3516,2744 3527,2733 3527,2503 3529,2501 3770,2501 3744,2377 3670,2195 3666,2188
SW1 on Top Layer (solid): 3445,2033 3397,1983 2965,1983 2962,1986 2962,2186 2957,2191 2844,2191 2838,2197 2838,2343 2947,2343 2947,2290 2960,2277 3148,2277 3155,2270 3155,2236 3167,2224 3222,2224 3223,2223 3223,2187 3213,2177 3183,2177 3174,2168 3174,2132 3165,2123 3165,2054 3169,2050 3198,2050 3201,2053 3201,2081 3201,2124 3202,2125 3223,2125 3226,2128 3226,2161 3249,2184 3249,2221 3250,2222 3271,2222 3272,2221 3272,2185 3276,2181 3281,2181 3284,2178 3284,2123 3277,2123 3275,2121 3275,2083 3280,2078 3318,2078 3323,2083 3323,2109 3326,2112 3468,2112 3473,2107 3473,2063 3465,2057
NONET on Top Layer (solid): 3019,3204 3049,3205 3074,3177 3115,3177 3178,3114 3178,3059 3177,3058 3132,3058 3070,3120 3019,3120
GND on Top Layer (solid): 1519,3727 1500,3708 1500,1592 1556,1536 3656,1536 3849,1729 3849,3799 3827,3821 1500,3821
LX on Bottom Layer (solid): 2738,2190 2739,2189 2784,2189 2788,2193 2788,2377 2788,2426 2787,2427 2637,2427 2634,2424 2634,2317 2640,2311 2728,2311 2730,2309 2730,2198
R32_2 on Bottom Layer (solid): 2977,2920 3058,2920 3061,2917 3061,2717 3058,2714 2976,2714 2974,2716 2974,2917
NONET on Bottom Layer (solid): 3182,3082 3187,2688 3164,2688 3164,3087 3177,3087 3182,3087 3182,3083
SW1 on Bottom Layer (solid): 2947.04,2270 2946.04,2271 2845.04,2271 2843.04,2273 2843.04,2405 2847.04,2409 3056.04,2409 3059.04,2406 3059.04,2348 3058.04,2347 2949.04,2347 2947.04,2345 2947.04,2270
GND on Bottom Layer (solid): 3739,3830 3720,3849 1604,3849 1548,3793 1548,1693 1741,1500 3811,1500 3833,1522 3833,3849

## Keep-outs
Keep-Out Layer:
  circle w10: c2705.68,2690.67 r1082.68

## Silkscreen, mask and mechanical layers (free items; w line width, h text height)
Top Overlay:
  circle w8: c2712.68,2690.67 r984.25
  text "GND" at 1996,3098.5 h35
  text "DEBUG" at 1989,3000.72 h35
  text "SCL" at 1989,2902.95 h35
  text "SDA" at 1989,2805.17 h35
  text "GND" at 2246,2711.5 h35
  text "VBUS" at 2246,2613.72 h35
  text "CC2" at 1989,2511.83 h35
  text "DP" at 1989,2414.06 h35
  text "DM" at 1989,2316.28 h35
  text "CC1" at 1989,2218.5 h35
Bottom Overlay:
  text "IP6802B_MPP25_DEMO_V1.3" at 3147,2490.71 h60
  text "2025/09/22" at 3151.1,2378.92 h45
